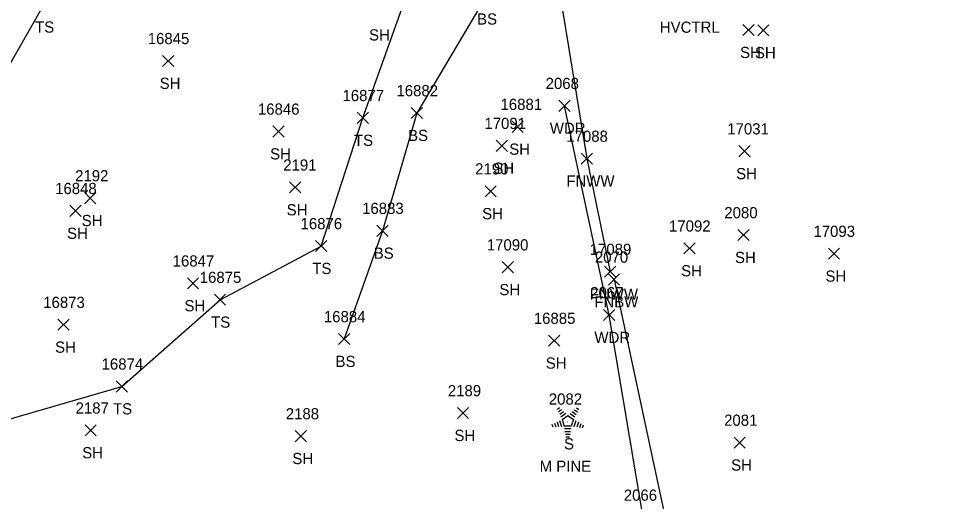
# Model space of a CAD drawing. Extents: x 1482574 to 1485769, y 580696 to 595649.
# Drawn here: x 1484852.1 to 1485016, y 582821.1 to 582907.4 of the extents above; entities that cross this region are included whole.
import ezdxf

# ---------------------------------------------------------------- set-up
doc = ezdxf.new("R2010")
doc.units = 0
for name, color, linetype in [('C_A', 7, 'Continuous'), ('L_A', 7, 'Continuous'), ('L_C', 7, 'Continuous'), ('L_I', 7, 'Continuous'), ('L_TIC', 7, 'Continuous'), ('LAWA', 7, 'Continuous'), ('LELB', 7, 'Continuous'), ('LFNC', 7, 'Continuous'), ('LTC', 7, 'Continuous')]:
    doc.layers.add(name, color=color, linetype=linetype)

msp = doc.modelspace()

# ---------------------------------------------------------------- linework, layer by layer
at = {"layer": 'L_TIC'}
for points in [[(1484981.55, 582904.33), (1484983.55, 582906.33)], [(1484983.55, 582904.33), (1484981.55, 582906.33)], [(1484984.21, 582904.28), (1484986.21, 582906.28)], [(1484986.21, 582904.28), (1484984.21, 582906.28)], [(1484877.82, 582898.81), (1484879.82, 582900.81)], [(1484879.82, 582898.81), (1484877.82, 582900.81)], [(1484922.26, 582889.5), (1484924.26, 582891.5)], [(1484924.26, 582889.5), (1484922.26, 582891.5)], [(1484948.67, 582890.79), (1484950.67, 582892.79)], [(1484950.67, 582890.79), (1484948.67, 582892.79)], [(1484912.62, 582888.63), (1484914.62, 582890.63)], [(1484914.62, 582888.63), (1484912.62, 582890.63)], [(1484897.56, 582886.21), (1484899.56, 582888.21)], [(1484899.56, 582886.21), (1484897.56, 582888.21)], [(1484940.3, 582887.05), (1484942.3, 582889.05)], [(1484942.3, 582887.05), (1484940.3, 582889.05)], [(1484937.45, 582883.65), (1484939.45, 582885.65)], [(1484939.45, 582883.65), (1484937.45, 582885.65)], [(1484952.65, 582881.36), (1484954.65, 582883.36)], [(1484954.65, 582881.36), (1484952.65, 582883.36)], [(1484980.85, 582882.68), (1484982.85, 582884.68)], [(1484982.85, 582882.68), (1484980.85, 582884.68)], [(1484900.52, 582876.22), (1484902.52, 582878.22)], [(1484902.52, 582876.22), (1484900.52, 582878.22)], [(1484935.47, 582875.52), (1484937.47, 582877.52)], [(1484937.47, 582875.52), (1484935.47, 582877.52)], [(1484863.89, 582874.3), (1484865.89, 582876.3)], [(1484865.89, 582874.3), (1484863.89, 582876.3)], [(1484861.27, 582872.02), (1484863.27, 582874.02)], [(1484863.27, 582872.02), (1484861.27, 582874.02)], [(1484916.13, 582868.47), (1484918.13, 582870.47)], [(1484918.13, 582868.47), (1484916.13, 582870.47)], [(1484980.64, 582867.7), (1484982.64, 582869.7)], [(1484982.64, 582867.7), (1484980.64, 582869.7)], [(1484905.18, 582865.74), (1484907.18, 582867.74)], [(1484907.18, 582865.74), (1484905.18, 582867.74)], [(1484971.01, 582865.32), (1484973.01, 582867.32)], [(1484973.01, 582865.32), (1484971.01, 582867.32)], [(1484996.82, 582864.37), (1484998.82, 582866.37)], [(1484998.82, 582864.37), (1484996.82, 582866.37)], [(1484938.53, 582861.95), (1484940.53, 582863.95)], [(1484940.53, 582861.95), (1484938.53, 582863.95)], [(1484956.84, 582861.15), (1484958.84, 582863.15)], [(1484958.84, 582861.15), (1484956.84, 582863.15)], [(1484882.27, 582859.08), (1484884.27, 582861.08)], [(1484884.27, 582859.08), (1484882.27, 582861.08)], [(1484957.52, 582859.76), (1484959.52, 582861.76)], [(1484959.52, 582859.76), (1484957.52, 582861.76)], [(1484887.1, 582856.15), (1484889.1, 582858.15)], [(1484889.1, 582856.15), (1484887.1, 582858.15)], [(1484956.64, 582853.41), (1484958.64, 582855.41)], [(1484958.64, 582853.41), (1484956.64, 582855.41)], [(1484859.13, 582851.68), (1484861.13, 582853.68)], [(1484861.13, 582851.68), (1484859.13, 582853.68)], [(1484909.3, 582849.13), (1484911.3, 582851.13)], [(1484911.3, 582849.13), (1484909.3, 582851.13)], [(1484946.82, 582848.83), (1484948.82, 582850.83)], [(1484948.82, 582848.83), (1484946.82, 582850.83)], [(1484869.56, 582840.66), (1484871.56, 582842.66)], [(1484871.56, 582840.66), (1484869.56, 582842.66)], [(1484930.52, 582835.9), (1484932.52, 582837.9)], [(1484932.52, 582835.9), (1484930.52, 582837.9)], [(1484863.99, 582832.81), (1484865.99, 582834.8)], [(1484865.99, 582832.81), (1484863.99, 582834.8)], [(1484901.54, 582831.78), (1484903.54, 582833.77)], [(1484903.54, 582831.78), (1484901.54, 582833.77)], [(1484979.96, 582830.62), (1484981.96, 582832.62)], [(1484981.96, 582830.62), (1484979.96, 582832.62)]]:
    msp.add_lwpolyline(points, dxfattribs=at)
at = {"layer": 'LAWA'}
msp.add_lwpolyline([(1484963.7, 582818.23), (1484957.64, 582854.41), (1484949.67, 582891.79)], dxfattribs=at)
at = {"layer": 'LELB'}
for points in [[(1484930.07, 582958.37), (1484898.4, 582986.07), (1484885.55, 582979.46), (1484884.78, 582958.51), (1484871.19, 582937.25), (1484856.63, 582909.87), (1484844.08, 582888.03), (1484828.7, 582873.63), (1484804.55, 582861.77), (1484803.54, 582840.27), (1484830.22, 582829.96), (1484870.56, 582841.66), (1484888.1, 582857.15), (1484906.18, 582866.74), (1484913.62, 582889.63), (1484923, 582915.85), (1484936.07, 582941.35)], [(1484936.07, 582941.35), (1484935.6, 582911.3), (1484923.26, 582890.5), (1484917.13, 582869.47), (1484910.3, 582850.13)]]:
    msp.add_lwpolyline(points, dxfattribs=at)
at = {"layer": 'LFNC'}
for points in [[(1484946.69, 582924.9), (1484953.65, 582882.36), (1484957.84, 582862.15)], [(1484958.52, 582860.76), (1484968.5, 582814.28), (1485001.17, 582815.23), (1485022.33, 582812.67), (1485033.43, 582808.96), (1485053.76, 582812.4)]]:
    msp.add_lwpolyline(points, dxfattribs=at)
at = {"layer": 'LTC'}
for p, q in [((1484948.39, 582837.61), (1484948.75, 582837.87)), ((1484948.6, 582837.15), (1484949.13, 582837.53)), ((1484951.42, 582837.5), (1484951.97, 582837.1)), ((1484951.79, 582837.85), (1484952.21, 582837.55)), ((1484948.81, 582836.68), (1484949.51, 582837.19)), ((1484949.02, 582836.21), (1484949.9, 582836.85)), ((1484949.24, 582835.76), (1484950.26, 582836.49)), ((1484949.24, 582835.76), (1484949.63, 582834.57)), ((1484950.26, 582836.49), (1484951.25, 582835.77)), ((1484950.68, 582836.81), (1484951.49, 582836.22)), ((1484951.25, 582835.77), (1484950.86, 582834.57)), ((1484951.05, 582837.15), (1484951.73, 582836.66)), ((1484947.42, 582834.89), (1484947.58, 582834.42)), ((1484947.88, 582835.11), (1484948.09, 582834.46)), ((1484948.33, 582835.32), (1484948.61, 582834.49)), ((1484948.79, 582835.54), (1484949.12, 582834.52)), ((1484950.86, 582834.57), (1484949.63, 582834.57)), ((1484950.82, 582834.07), (1484949.68, 582834.07)), ((1484951.69, 582835.5), (1484951.35, 582834.46)), ((1484952.14, 582835.25), (1484951.85, 582834.36)), ((1484952.58, 582835), (1484952.34, 582834.27)), ((1484953.02, 582834.75), (1484952.84, 582834.17)), ((1484950.74, 582833.57), (1484949.75, 582833.57)), ((1484950.66, 582833.07), (1484949.82, 582833.07)), ((1484950.57, 582832.57), (1484949.9, 582832.57))]:
    msp.add_line(p, q, dxfattribs=at)

# ---------------------------------------------------------------- texts
at = {"layer": 'C_A'}
msp.add_text('HVCTRL', height=2, dxfattribs=at).set_placement((1484966.7, 582904.84))
at = {"layer": 'L_A'}
for s, p in [('BS', (1484934.04, 582906.3)), ('TS', (1484855.04, 582904.87)), ('SH', (1484914.73, 582903.46)), ('SH', (1484981.04, 582900.33)), ('SH', (1484983.7, 582900.28)), ('SH', (1484877.31, 582894.81)), ('WDR', (1484947.04, 582886.79)), ('TS', (1484912.03, 582884.63)), ('BS', (1484921.71, 582885.5)), ('SH', (1484939.79, 582883.05)), ('SH', (1484897.05, 582882.21)), ('SH', (1484936.94, 582879.65)), ('SH', (1484980.34, 582878.68)), ('FNWW', (1484949.99, 582877.36)), ('SH', (1484900.01, 582872.22)), ('SH', (1484934.95, 582871.52)), ('SH', (1484863.38, 582870.3)), ('SH', (1484860.76, 582868.02)), ('BS', (1484915.57, 582864.47)), ('SH', (1484980.13, 582863.7)), ('TS', (1484904.59, 582861.74)), ('SH', (1484970.5, 582861.32)), ('SH', (1484996.3, 582860.37)), ('SH', (1484938.02, 582857.95)), ('FNWW', (1484954.19, 582857.15)), ('SH', (1484881.75, 582855.08)), ('FNBW', (1484954.99, 582855.76)), ('TS', (1484886.51, 582852.15)), ('WDR', (1484955.01, 582849.41)), ('SH', (1484858.62, 582847.68)), ('BS', (1484908.74, 582845.13)), ('SH', (1484946.31, 582844.83)), ('TS', (1484868.97, 582836.66)), ('SH', (1484930, 582831.9)), ('S', (1484949.58, 582830.4)), ('SH', (1484863.47, 582828.81)), ('SH', (1484901.03, 582827.78)), ('SH', (1484979.45, 582826.62))]:
    msp.add_text(s, height=2, dxfattribs=at).set_placement(p)
at = {"layer": 'L_C'}
msp.add_text('M PINE', height=2, dxfattribs=at).set_placement((1484945.22, 582826.4))
at = {"layer": 'L_I'}
for s, p in [('16845', (1484875.18, 582902.81)), ('2068', (1484946.29, 582894.79)), ('16877', (1484909.98, 582892.63)), ('16882', (1484919.63, 582893.5)), ('16881', (1484938.23, 582891.05)), ('16846', (1484894.87, 582890.21)), ('17091', (1484935.35, 582887.65)), ('17031', (1484978.75, 582886.68)), ('17088', (1484949.98, 582885.36)), ('2191', (1484899.4, 582880.22)), ('2190', (1484933.69, 582879.52)), ('2192', (1484862.2, 582878.3)), ('16848', (1484858.63, 582876.02)), ('16883', (1484913.49, 582872.47)), ('2080', (1484978.22, 582871.7)), ('16876', (1484902.49, 582869.74)), ('17092', (1484968.34, 582869.32)), ('17093', (1484994.15, 582868.37)), ('17090', (1484935.78, 582865.95)), ('17089', (1484954.17, 582865.15)), ('16847', (1484879.63, 582863.08)), ('2070', (1484955.09, 582863.76)), ('16875', (1484884.47, 582860.15)), ('2067', (1484954.26, 582857.41)), ('16873', (1484856.5, 582855.68)), ('16884', (1484906.66, 582853.13)), ('16885', (1484944.18, 582852.83)), ('16874', (1484866.93, 582844.66)), ('2189', (1484928.81, 582839.9)), ('2187', (1484862.29, 582836.8)), ('2082', (1484946.86, 582838.4)), ('2188', (1484899.85, 582835.77)), ('2081', (1484978.19, 582834.62)), ('2066', (1484960.26, 582821.23))]:
    msp.add_text(s, height=2, dxfattribs=at).set_placement(p)
at = {"layer": 'LTC'}
msp.add_text('.', height=1.04, rotation=270, dxfattribs=at).set_placement((1484950.14, 582835.51))

doc.saveas('drawing.dxf')
